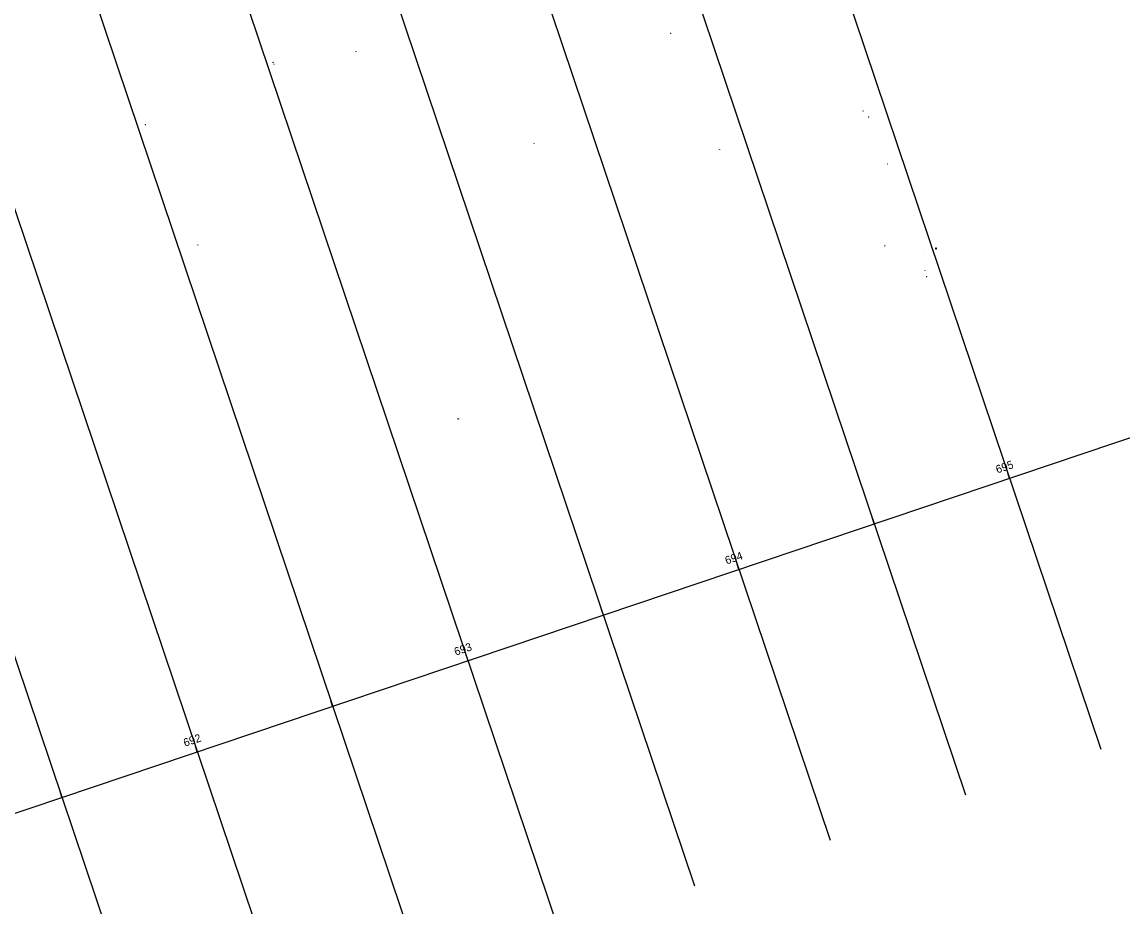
# Model space of a CAD drawing. Extents: x 2175772 to 2185556, y 721391 to 722853.
# Drawn here: x 2178867 to 2179252, y 721714.1 to 722023.6 of the extents above; entities that cross this region are included whole.
import ezdxf

# ---------------------------------------------------------------- set-up
doc = ezdxf.new("R2010")
doc.units = 0
for name, color, linetype in [('DR_X_Erosion_Control', 7, 'Continuous'), ('DT_X_Triangles', 7, 'Continuous'), ('RD_X_Cells', 7, 'Continuous'), ('SV_X_Shot_Marker', 7, 'Continuous'), ('SV_X_Text_Comment', 7, 'Continuous'), ('SV_X_Text_Description', 7, 'Continuous'), ('VG_X_Tree_Line_Rt', 7, 'Continuous')]:
    doc.layers.add(name, color=color, linetype=linetype)

msp = doc.modelspace()

# ---------------------------------------------------------------- linework, layer by layer
at = {"layer": 'DR_X_Erosion_Control'}
for p, q in [((2179186.9, 721944.26), (2179186.9, 721944.26)), ((2179186.9, 721944.26), (2179186.9, 721944.26)), ((2179019.68, 721884.65), (2179019.68, 721884.65)), ((2179019.68, 721884.65), (2179019.68, 721884.65))]:
    msp.add_line(p, q, dxfattribs=at)
for points in [[(2179186.79, 721944.26), (2179186.8, 721944.18), (2179186.81, 721944.26), (2179186.83, 721944.18), (2179186.84, 721944.26)], [(2179186.79, 721944.26), (2179186.8, 721944.18), (2179186.81, 721944.26), (2179186.83, 721944.18), (2179186.84, 721944.26)], [(2179186.9, 721944.26), (2179186.86, 721944.26), (2179186.86, 721944.18), (2179186.9, 721944.18)], [(2179186.9, 721944.26), (2179186.86, 721944.26), (2179186.86, 721944.18), (2179186.9, 721944.18)], [(2179186.86, 721944.22), (2179186.89, 721944.22)], [(2179186.86, 721944.22), (2179186.89, 721944.22)], [(2179186.87, 721944.3), (2179186.87, 721944.38), (2179186.9, 721944.3), (2179186.93, 721944.38), (2179186.93, 721944.3)], [(2179186.87, 721944.3), (2179186.87, 721944.38), (2179186.9, 721944.3), (2179186.93, 721944.38), (2179186.93, 721944.3)], [(2179186.92, 721944.26), (2179186.92, 721944.18), (2179186.96, 721944.18)], [(2179186.92, 721944.26), (2179186.92, 721944.18), (2179186.96, 721944.18)], [(2179186.98, 721944.26), (2179186.98, 721944.18), (2179187.02, 721944.18)], [(2179186.98, 721944.26), (2179186.98, 721944.18), (2179187.02, 721944.18)], [(2179019.57, 721884.65), (2179019.58, 721884.57), (2179019.59, 721884.65), (2179019.6, 721884.57), (2179019.61, 721884.65)], [(2179019.57, 721884.65), (2179019.58, 721884.57), (2179019.59, 721884.65), (2179019.6, 721884.57), (2179019.61, 721884.65)], [(2179019.67, 721884.65), (2179019.64, 721884.65), (2179019.64, 721884.57), (2179019.68, 721884.57)], [(2179019.67, 721884.65), (2179019.64, 721884.65), (2179019.64, 721884.57), (2179019.68, 721884.57)], [(2179019.64, 721884.61), (2179019.66, 721884.61)], [(2179019.64, 721884.61), (2179019.66, 721884.61)], [(2179019.65, 721884.69), (2179019.65, 721884.77), (2179019.68, 721884.69), (2179019.71, 721884.77), (2179019.71, 721884.69)], [(2179019.65, 721884.69), (2179019.65, 721884.77), (2179019.68, 721884.69), (2179019.71, 721884.77), (2179019.71, 721884.69)], [(2179019.7, 721884.65), (2179019.7, 721884.57), (2179019.73, 721884.57)], [(2179019.7, 721884.65), (2179019.7, 721884.57), (2179019.73, 721884.57)], [(2179019.76, 721884.65), (2179019.76, 721884.57), (2179019.79, 721884.57)], [(2179019.76, 721884.65), (2179019.76, 721884.57), (2179019.79, 721884.57)]]:
    msp.add_lwpolyline(points, dxfattribs=at)
for centre, start, end in [((2179186.9, 721944.26), 164.0021, 196.0591), ((2179186.9, 721944.26), 164.0021, 196.0591), ((2179186.9, 721944.26), 118.9866, 150.9578), ((2179186.9, 721944.26), 118.9866, 150.9578), ((2179186.9, 721944.26), 208.9866, 240.9578), ((2179186.9, 721944.26), 208.9866, 240.9578), ((2179186.9, 721944.26), 73.9409, 105.9366), ((2179186.9, 721944.26), 73.9409, 105.9366), ((2179186.9, 721944.26), 253.9409, 285.9366), ((2179186.9, 721944.26), 253.9409, 285.9366), ((2179186.9, 721944.26), 28.9866, 60.9578), ((2179186.9, 721944.26), 28.9866, 60.9578), ((2179186.9, 721944.26), 298.9866, 331.0134), ((2179186.9, 721944.26), 298.9866, 331.0134), ((2179186.9, 721944.26), 344.0021, 15.9979), ((2179186.9, 721944.26), 344.0021, 15.9979), ((2179019.68, 721884.65), 164.0021, 196.0591), ((2179019.68, 721884.65), 164.0021, 196.0591), ((2179019.68, 721884.65), 118.9866, 150.9578), ((2179019.68, 721884.65), 118.9866, 150.9578), ((2179019.68, 721884.65), 208.9866, 240.9578), ((2179019.68, 721884.65), 208.9866, 240.9578), ((2179019.68, 721884.65), 73.9409, 105.9366), ((2179019.68, 721884.65), 73.9409, 105.9366), ((2179019.68, 721884.65), 253.9409, 285.9366), ((2179019.68, 721884.65), 253.9409, 285.9366), ((2179019.68, 721884.65), 28.9866, 60.9578), ((2179019.68, 721884.65), 28.9866, 60.9578), ((2179019.68, 721884.65), 298.9866, 331.0134), ((2179019.68, 721884.65), 298.9866, 331.0134), ((2179019.68, 721884.65), 344.0021, 15.9979), ((2179019.68, 721884.65), 344.0021, 15.9979)]:
    msp.add_arc(centre, 0.15, start, end, dxfattribs=at)
at = {"layer": 'DT_X_Triangles'}
for p, q in [((2178697.33, 721690.31), (2180444.45, 722278.43)), ((2179212.68, 721863.79), (2179212.04, 721865.68)), ((2179165.29, 721847.84), (2179164.65, 721849.73)), ((2179117.9, 721831.89), (2179117.27, 721833.78)), ((2179070.52, 721815.93), (2179069.88, 721817.83)), ((2179023.13, 721799.98), (2179022.49, 721801.88)), ((2178975.74, 721784.03), (2178975.1, 721785.93)), ((2178928.35, 721768.08), (2178927.72, 721769.97)), ((2178880.97, 721752.13), (2178880.33, 721754.02))]:
    msp.add_line(p, q, dxfattribs=at)
at = {"layer": 'RD_X_Cells'}
for p, q in [((2179094.03, 722019.52), (2179094.09, 722019.59)), ((2179094.03, 722019.59), (2179094.09, 722019.52)), ((2179094.03, 722019.52), (2179094.09, 722019.59)), ((2179094.03, 722019.59), (2179094.09, 722019.52)), ((2178983.84, 722013.15), (2178983.91, 722013.22)), ((2178983.84, 722013.22), (2178983.91, 722013.15)), ((2178983.84, 722013.15), (2178983.91, 722013.22)), ((2178983.84, 722013.22), (2178983.91, 722013.15)), ((2178955.19, 722008.77), (2178955.26, 722008.84)), ((2178955.19, 722008.84), (2178955.26, 722008.77)), ((2178955.19, 722008.77), (2178955.26, 722008.84)), ((2178955.19, 722008.84), (2178955.26, 722008.77)), ((2179163.34, 721990.29), (2179163.41, 721990.36)), ((2179163.34, 721990.36), (2179163.41, 721990.29)), ((2179163.34, 721990.29), (2179163.41, 721990.36)), ((2179163.34, 721990.36), (2179163.41, 721990.29)), ((2178910.16, 721987.57), (2178910.23, 721987.63)), ((2178910.16, 721987.63), (2178910.23, 721987.57)), ((2178910.16, 721987.57), (2178910.23, 721987.63)), ((2178910.16, 721987.63), (2178910.23, 721987.57)), ((2179169.96, 721973.87), (2179170.03, 721973.94)), ((2179169.96, 721973.94), (2179170.03, 721973.87)), ((2179169.96, 721973.87), (2179170.03, 721973.94)), ((2179169.96, 721973.94), (2179170.03, 721973.87)), ((2179179.21, 721955.8), (2179179.28, 721955.87)), ((2179179.21, 721955.87), (2179179.28, 721955.8)), ((2179179.21, 721955.8), (2179179.28, 721955.87)), ((2179179.21, 721955.87), (2179179.28, 721955.8)), ((2179182.5, 721943.39), (2179182.56, 721943.46)), ((2179182.5, 721943.46), (2179182.56, 721943.39)), ((2179182.5, 721943.39), (2179182.56, 721943.46)), ((2179182.5, 721943.46), (2179182.56, 721943.39))]:
    msp.add_line(p, q, dxfattribs=at)
at = {"layer": 'SV_X_Shot_Marker'}
for points in [[(2179053.16, 722337.66), (2179244.58, 721769.01)], [(2179005.78, 722321.71), (2179197.19, 721753.06)], [(2178958.39, 722305.76), (2179149.81, 721737.11)], [(2178911, 722289.81), (2179102.42, 721721.16)], [(2178863.61, 722273.85), (2179055.03, 721705.21)], [(2178816.23, 722257.9), (2179007.64, 721689.26)], [(2178768.84, 722241.95), (2178960.26, 721673.3)], [(2178721.45, 722226), (2178912.87, 721657.35)]]:
    msp.add_lwpolyline(points, dxfattribs=at)
at = {"layer": 'SV_X_Text_Comment'}
for p, q in [((2179161.46, 721992.41), (2179161.41, 721992.4)), ((2179161.46, 721992.41), (2179161.41, 721992.4)), ((2179161.44, 721992.38), (2179161.43, 721992.43)), ((2179161.44, 721992.38), (2179161.43, 721992.43)), ((2179161.43, 721992.4), (2179161.43, 721992.4)), ((2179161.43, 721992.4), (2179161.43, 721992.4)), ((2179046.29, 721981.07), (2179046.25, 721981.07)), ((2179046.29, 721981.07), (2179046.25, 721981.07)), ((2179046.27, 721981.04), (2179046.27, 721981.09)), ((2179046.27, 721981.04), (2179046.27, 721981.09)), ((2179046.27, 721981.07), (2179046.27, 721981.07)), ((2179046.27, 721981.07), (2179046.27, 721981.07)), ((2179111.15, 721978.87), (2179111.11, 721978.85)), ((2179111.15, 721978.87), (2179111.11, 721978.85)), ((2179111.14, 721978.84), (2179111.12, 721978.88)), ((2179111.14, 721978.84), (2179111.12, 721978.88)), ((2179111.13, 721978.86), (2179111.13, 721978.86)), ((2179111.13, 721978.86), (2179111.13, 721978.86)), ((2178928.56, 721945.5), (2178928.52, 721945.48)), ((2178928.56, 721945.5), (2178928.52, 721945.48)), ((2178928.55, 721945.47), (2178928.53, 721945.51)), ((2178928.55, 721945.47), (2178928.53, 721945.51)), ((2178928.54, 721945.49), (2178928.54, 721945.49)), ((2178928.54, 721945.49), (2178928.54, 721945.49)), ((2179182.96, 721936.63), (2179183.01, 721936.63)), ((2179182.96, 721936.63), (2179183.01, 721936.63)), ((2179182.99, 721936.66), (2179182.99, 721936.6)), ((2179182.99, 721936.66), (2179182.99, 721936.6)), ((2179182.99, 721936.63), (2179182.99, 721936.63)), ((2179182.99, 721936.63), (2179182.99, 721936.63)), ((2179183.6, 721934.52), (2179183.65, 721934.52)), ((2179183.6, 721934.52), (2179183.65, 721934.52)), ((2179183.63, 721934.54), (2179183.63, 721934.49)), ((2179183.63, 721934.54), (2179183.63, 721934.49)), ((2179183.63, 721934.52), (2179183.63, 721934.52)), ((2179183.63, 721934.52), (2179183.63, 721934.52)), ((2178874.51, 721928.4), (2178874.46, 721928.39)), ((2178874.51, 721928.4), (2178874.46, 721928.39)), ((2178874.49, 721928.37), (2178874.48, 721928.42)), ((2178874.49, 721928.37), (2178874.48, 721928.42)), ((2178874.48, 721928.39), (2178874.48, 721928.39)), ((2178874.48, 721928.39), (2178874.48, 721928.39))]:
    msp.add_line(p, q, dxfattribs=at)
at = {"layer": 'SV_X_Text_Description'}
msp.add_lwpolyline([(2178954.78, 722009.35), (2178954.84, 722009.31), (2178954.91, 722009.35), (2178954.91, 722009.42), (2178954.84, 722009.46), (2178954.78, 722009.42), (2178954.78, 722009.35)], dxfattribs=at)
msp.add_lwpolyline([(2178954.78, 722009.35), (2178954.84, 722009.31), (2178954.91, 722009.35), (2178954.91, 722009.42), (2178954.84, 722009.46), (2178954.78, 722009.42), (2178954.78, 722009.35)], dxfattribs=at)
at = {"layer": 'VG_X_Tree_Line_Rt'}
for p, q in [((2179168.94, 721945.23), (2179168.99, 721945.23)), ((2179168.94, 721945.23), (2179168.99, 721945.23)), ((2179168.96, 721945.26), (2179168.96, 721945.21)), ((2179168.96, 721945.26), (2179168.96, 721945.21)), ((2179168.96, 721945.23), (2179168.96, 721945.23)), ((2179168.96, 721945.23), (2179168.96, 721945.23))]:
    msp.add_line(p, q, dxfattribs=at)

# ---------------------------------------------------------------- texts
at = {"layer": 'DT_X_Triangles'}
for s, p in [('695', (2179208.37, 721865.5)), ('694', (2179113.62, 721833.61)), ('693', (2179018.81, 721801.69)), ('692', (2178924.06, 721769.8))]:
    msp.add_text(s, height=2.8, rotation=18.6042, dxfattribs=at).set_placement(p)

doc.saveas('drawing.dxf')
